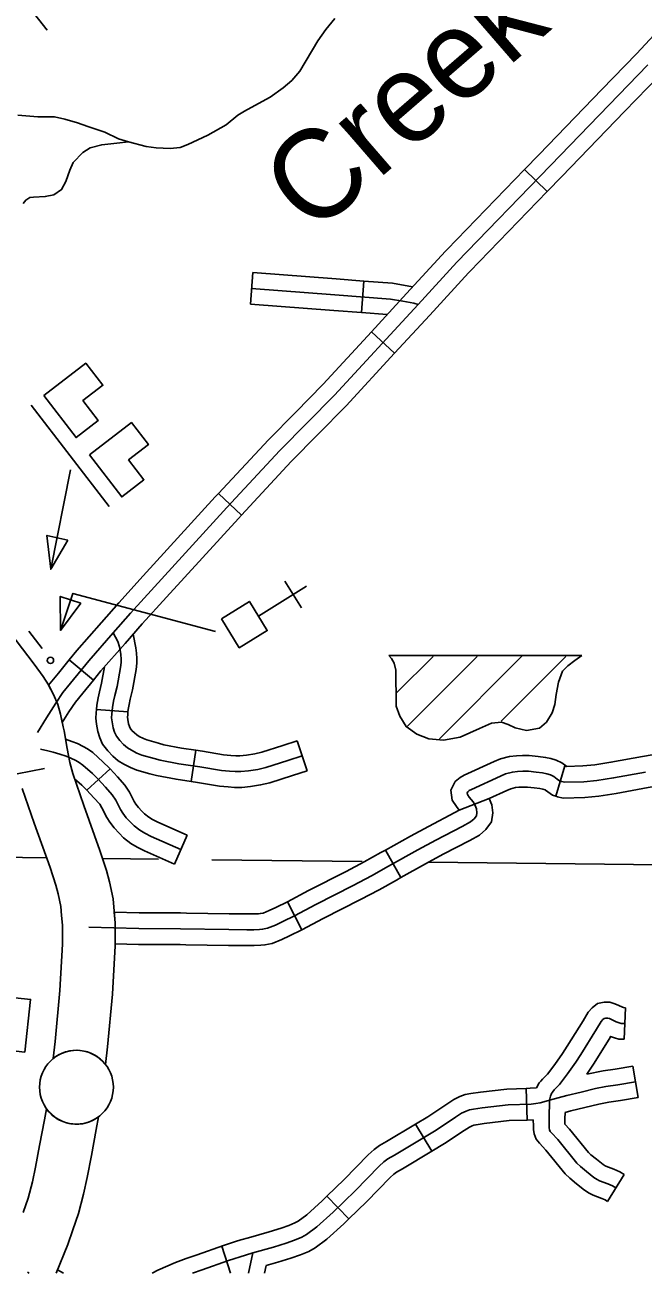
# Model space of a CAD drawing. Extents: x -3711 to 825, y -151 to 1050.
# Drawn here: x -2824.2 to -2791.3, y 120.4 to 186.7 of the extents above; entities that cross this region are included whole.
import ezdxf

# ---------------------------------------------------------------- set-up
doc = ezdxf.new("R2010")
doc.units = 0
for name, color, linetype in [('Level 10', 7, 'Continuous'), ('Level 24', 7, 'Continuous'), ('Level 31', 7, 'Continuous'), ('Level 32', 7, 'Continuous'), ('Level 35', 7, 'Continuous'), ('Level 40', 7, 'Continuous'), ('Level 5', 7, 'Continuous'), ('Level 57', 7, 'Continuous'), ('Level 58', 7, 'Continuous')]:
    doc.layers.add(name, color=color, linetype=linetype)

msp = doc.modelspace()

# ---------------------------------------------------------------- linework, layer by layer
at = {"layer": 'Level 10'}
for points in [[(-2819.879, 131.44), (-2819.776, 132.369), (-2819.516, 135.167), (-2819.367, 137.747), (-2819.367, 138.733), (-2819.367, 138.973), (-2819.42, 139.588), (-2819.476, 140.244), (-2819.669, 141.14), (-2819.821, 141.749), (-2820.181, 142.818), (-2821.029, 145.194), (-2821.623, 146.905), (-2821.768, 147.493), (-2821.872, 147.946), (-2821.952, 148.422), (-2821.973, 148.548), (-2822.085, 149.176), (-2822.127, 149.378), (-2822.27, 150.058), (-2822.417, 150.579), (-2822.639, 151.095), (-2822.907, 151.61), (-2823.201, 152.051), (-2823.664, 152.707), (-2825.611, 155.235)], [(-2824.312, 146.108), (-2823.673, 144.264), (-2822.829, 141.899), (-2822.512, 140.961), (-2822.399, 140.506), (-2822.253, 139.829), (-2822.212, 139.348), (-2822.169, 138.851), (-2822.169, 138.733), (-2822.169, 137.828), (-2822.31, 135.377), (-2822.563, 132.654), (-2822.664, 131.751), (-2822.518, 131.858), (-2822.335, 131.971), (-2822.164, 132.048), (-2821.969, 132.115), (-2821.783, 132.157), (-2821.573, 132.189), (-2821.363, 132.192), (-2821.129, 132.173), (-2820.927, 132.13), (-2820.748, 132.072), (-2820.6, 132.009), (-2820.433, 131.92), (-2820.289, 131.83), (-2820.153, 131.721), (-2820.032, 131.612), (-2819.879, 131.44)], [(-2824.256, 123.57), (-2823.995, 124.331), (-2823.769, 125.198), (-2823.598, 125.99), (-2823.387, 127.13), (-2823.123, 128.498), (-2823.016, 129.084), (-2822.897, 128.927), (-2822.766, 128.792), (-2822.635, 128.684), (-2822.48, 128.572), (-2822.322, 128.483), (-2822.152, 128.402), (-2821.955, 128.336), (-2821.72, 128.286), (-2821.511, 128.267), (-2821.291, 128.271), (-2821.098, 128.29), (-2820.901, 128.332), (-2820.723, 128.394), (-2820.542, 128.475), (-2820.391, 128.56), (-2820.244, 128.665)], [(-2820.244, 128.665), (-2820.369, 127.98), (-2820.633, 126.609), (-2820.851, 125.439), (-2821.042, 124.549), (-2821.311, 123.522), (-2821.61, 122.647), (-2821.887, 121.868), (-2822.501, 120.355)]]:
    msp.add_lwpolyline(points, dxfattribs=at)
at = {"layer": 'Level 24'}
msp.add_circle((-2821.424, 130.231), 1.961, dxfattribs=at)
at = {"layer": 'Level 31'}
for p, q in [((-2796.401, 177.83), (-2797.609, 179)), ((-2804.512, 169.242), (-2805.75, 170.38)), ((-2813.878, 161.784), (-2812.646, 160.64)), ((-2821.816, 152.936), (-2820.516, 151.871)), ((-2809.448, 138.591), (-2810.212, 140.089))]:
    msp.add_line(p, q, dxfattribs=at)
for points in [[(-2793.495, 183.253), (-2791.659, 185.153), (-2790.026, 186.902), (-2789.483, 187.534)], [(-2788.208, 186.439), (-2788.774, 185.78), (-2790.44, 183.995), (-2792.287, 182.085)], [(-2791.05, 184.574), (-2796.232, 179.213), (-2801.2, 174.086), (-2803.268, 171.837), (-2807.702, 167.016), (-2810.613, 164.064), (-2813.427, 161.034), (-2818.551, 155.421), (-2819.467, 154.375), (-2820.763, 152.896), (-2821.734, 151.711), (-2822.141, 151.206), (-2822.529, 150.643), (-2823.014, 149.866), (-2823.498, 149.09)], [(-2797.609, 179), (-2796.836, 179.798), (-2793.495, 183.253)], [(-2792.287, 182.085), (-2795.628, 178.629), (-2796.401, 177.83)], [(-2797.609, 179), (-2801.727, 174.75)], [(-2796.401, 177.83), (-2800.519, 173.58)], [(-2801.727, 174.75), (-2801.811, 174.663), (-2803.886, 172.406), (-2805.75, 170.38)], [(-2800.519, 173.58), (-2800.589, 173.508), (-2802.649, 171.268), (-2804.512, 169.242)], [(-2805.75, 170.38), (-2808.31, 167.596), (-2809.789, 166.096)], [(-2808.592, 164.916), (-2807.093, 166.436), (-2804.512, 169.242)], [(-2809.789, 166.096), (-2811.22, 164.645), (-2813.878, 161.784)], [(-2812.646, 160.64), (-2810.005, 163.482), (-2808.592, 164.916)], [(-2813.878, 161.784), (-2814.045, 161.603), (-2817.874, 157.409)], [(-2812.646, 160.64), (-2812.809, 160.464), (-2816.632, 156.276)], [(-2817.874, 157.409), (-2819.177, 155.981), (-2820.099, 154.929), (-2821.405, 153.439), (-2821.816, 152.936)], [(-2816.632, 156.276), (-2817.924, 154.86), (-2818.835, 153.821), (-2820.122, 152.352), (-2820.516, 151.871)], [(-2822.902, 151.601), (-2822.386, 152.241), (-2821.816, 152.936)], [(-2820.516, 151.871), (-2821.081, 151.181), (-2821.467, 150.703), (-2821.826, 150.181), (-2822.178, 149.618), (-2822.27, 150.058), (-2822.417, 150.579), (-2822.639, 151.095), (-2822.902, 151.601)], [(-2810.212, 140.089), (-2810.829, 139.786), (-2811.181, 139.619), (-2811.506, 139.489), (-2811.658, 139.459), (-2811.752, 139.449), (-2812.014, 139.438), (-2812.362, 139.438), (-2813.312, 139.451), (-2815.582, 139.486)], [(-2809.83, 139.34), (-2810.463, 139.03), (-2810.844, 138.848), (-2811.266, 138.68), (-2811.532, 138.627), (-2811.69, 138.61), (-2811.996, 138.597), (-2812.368, 138.597), (-2813.324, 138.61), (-2815.901, 138.65), (-2818.105, 138.663), (-2820.768, 138.733)], [(-2815.582, 139.486), (-2815.891, 139.491), (-2818.092, 139.504), (-2819.416, 139.539), (-2819.367, 138.973), (-2819.367, 137.856)], [(-2815.608, 137.805), (-2813.336, 137.77), (-2812.374, 137.756), (-2811.978, 137.756), (-2811.628, 137.772), (-2811.405, 137.795), (-2811.026, 137.871), (-2810.508, 138.077), (-2810.097, 138.273), (-2809.448, 138.591)], [(-2819.367, 137.856), (-2818.119, 137.823), (-2815.91, 137.81), (-2815.608, 137.805)]]:
    msp.add_lwpolyline(points, dxfattribs=at)
at = {"layer": 'Level 32'}
for p, q in [((-2812.181, 171.849), (-2812.052, 173.525)), ((-2806.28, 171.395), (-2806.151, 173.071)), ((-2818.689, 150.182), (-2820.366, 150.311)), ((-2809.69, 148.638), (-2809.166, 147.041)), ((-2815.081, 148.137), (-2815.335, 146.475)), ((-2795.947, 145.696), (-2795.463, 147.306)), ((-2819.627, 147.146), (-2820.869, 146.012)), ((-2799.481, 145.571), (-2801.077, 144.959)), ((-2815.534, 143.624), (-2816.218, 142.088)), ((-2804.186, 141.368), (-2805.006, 142.835)), ((-2792.237, 134.456), (-2792.307, 132.776)), ((-2791.851, 131.35), (-2791.568, 129.692)), ((-2797.524, 130.167), (-2797.466, 128.487)), ((-2803.407, 128.267), (-2802.542, 126.825)), ((-2792.318, 125.594), (-2793.203, 124.165)), ((-2808.113, 124.436), (-2806.943, 123.229)), ((-2813.697, 121.785), (-2813.24, 120.355))]:
    msp.add_line(p, q, dxfattribs=at)
for points in [[(-2812.052, 173.525), (-2807.623, 173.185), (-2806.151, 173.071)], [(-2812.116, 172.687), (-2807.688, 172.346), (-2804.735, 172.119), (-2804.082, 172.005), (-2803.486, 171.892), (-2803.268, 171.837)], [(-2806.151, 173.071), (-2804.631, 172.954), (-2803.555, 172.767)], [(-2812.181, 171.849), (-2807.752, 171.508), (-2806.28, 171.395)], [(-2806.28, 171.395), (-2804.913, 171.29)], [(-2809.428, 147.839), (-2810.191, 147.589), (-2811.36, 147.219), (-2811.789, 147.123), (-2812.278, 147.052), (-2812.684, 147.004), (-2812.994, 147.004), (-2813.292, 147.028), (-2813.721, 147.064), (-2814.865, 147.254), (-2815.984, 147.425), (-2816.972, 147.61), (-2817.288, 147.702), (-2817.947, 147.886), (-2818.21, 147.992), (-2818.5, 148.137), (-2818.711, 148.269), (-2818.922, 148.44), (-2819.119, 148.651), (-2819.304, 148.888), (-2819.396, 149.099), (-2819.475, 149.336), (-2819.528, 149.653), (-2819.554, 149.864), (-2819.541, 150.075), (-2819.514, 150.417), (-2819.449, 150.747), (-2819.383, 151.05), (-2819.264, 151.525), (-2819.08, 152.54), (-2819.053, 152.804), (-2819.053, 152.988), (-2819.067, 153.225), (-2819.093, 153.45), (-2819.132, 153.634), (-2819.225, 153.911), (-2819.467, 154.375)], [(-2818.689, 150.182), (-2818.68, 150.302), (-2818.626, 150.575), (-2818.564, 150.859), (-2818.442, 151.348), (-2818.247, 152.423), (-2818.213, 152.762), (-2818.213, 153.011), (-2818.229, 153.298), (-2818.263, 153.587), (-2818.415, 154.3)], [(-2820.366, 150.311), (-2820.349, 150.532), (-2820.271, 150.919), (-2820.201, 151.241), (-2820.086, 151.702), (-2819.928, 152.573)], [(-2815.335, 146.475), (-2816.125, 146.596), (-2817.168, 146.791), (-2817.519, 146.894), (-2818.217, 147.089), (-2818.555, 147.224), (-2818.912, 147.403), (-2819.201, 147.584), (-2819.496, 147.824), (-2819.759, 148.105), (-2820.032, 148.455), (-2820.181, 148.797), (-2820.293, 149.133), (-2820.36, 149.532), (-2820.398, 149.838), (-2820.379, 150.133), (-2820.366, 150.311)], [(-2815.081, 148.137), (-2815.843, 148.254), (-2816.777, 148.428), (-2817.057, 148.51), (-2817.676, 148.684), (-2817.865, 148.759), (-2818.088, 148.871), (-2818.221, 148.954), (-2818.347, 149.056), (-2818.479, 149.197), (-2818.575, 149.321), (-2818.61, 149.401), (-2818.656, 149.54), (-2818.696, 149.774), (-2818.71, 149.89), (-2818.702, 150.016), (-2818.689, 150.182)], [(-2819.627, 147.146), (-2819.679, 147.203), (-2820.001, 147.511), (-2820.56, 148.015), (-2820.838, 148.206), (-2821.066, 148.337), (-2821.373, 148.49), (-2821.678, 148.612), (-2822.005, 148.725)], [(-2809.69, 148.638), (-2810.449, 148.389), (-2811.578, 148.031), (-2811.942, 147.95), (-2812.388, 147.885), (-2812.733, 147.844), (-2812.96, 147.844), (-2813.223, 147.866), (-2813.617, 147.898), (-2814.732, 148.084), (-2815.081, 148.137)], [(-2815.876, 142.856), (-2817.458, 143.559), (-2817.796, 143.725), (-2818.055, 143.885), (-2818.361, 144.121), (-2818.551, 144.312), (-2818.78, 144.554), (-2818.958, 144.795), (-2819.085, 144.986), (-2819.34, 145.495), (-2819.518, 145.775), (-2819.874, 146.17), (-2820.281, 146.615), (-2820.573, 146.895), (-2821.082, 147.354), (-2821.285, 147.494), (-2821.463, 147.595), (-2821.718, 147.723), (-2821.972, 147.824), (-2822.303, 147.939), (-2822.656, 148.041), (-2822.954, 148.111), (-2823.334, 148.188)], [(-2795.463, 147.306), (-2795.418, 147.293), (-2795.376, 147.282), (-2794.514, 147.309), (-2793.865, 147.37), (-2793.015, 147.498), (-2791.329, 147.807), (-2790.001, 148.039)], [(-2801.077, 144.959), (-2801.227, 145.142), (-2801.451, 145.492), (-2801.526, 146.011), (-2801.296, 146.47), (-2801.032, 146.691), (-2800.811, 146.811), (-2799.22, 147.539), (-2798.891, 147.676), (-2798.413, 147.807), (-2798.041, 147.851), (-2797.714, 147.864), (-2797.353, 147.864), (-2796.889, 147.814), (-2796.488, 147.762), (-2796.208, 147.692), (-2795.931, 147.615), (-2795.619, 147.469), (-2795.368, 147.277), (-2795.463, 147.306)], [(-2824.57, 146.887), (-2823.131, 147.168)], [(-2820.869, 146.012), (-2820.882, 146.028), (-2821.145, 146.279), (-2821.524, 146.62)], [(-2815.534, 143.624), (-2817.102, 144.321), (-2817.39, 144.462), (-2817.576, 144.577), (-2817.804, 144.753), (-2817.949, 144.898), (-2818.134, 145.094), (-2818.27, 145.278), (-2818.357, 145.409), (-2818.607, 145.91), (-2818.846, 146.286), (-2819.251, 146.735), (-2819.627, 147.146)], [(-2809.166, 147.041), (-2809.933, 146.789), (-2811.141, 146.406), (-2811.637, 146.296), (-2812.168, 146.218), (-2812.634, 146.163), (-2813.027, 146.163), (-2813.36, 146.19), (-2813.825, 146.229), (-2814.997, 146.423), (-2815.335, 146.475)], [(-2809.83, 139.34), (-2808.704, 139.937), (-2806.709, 140.954), (-2805.739, 141.462), (-2804.832, 141.97), (-2803.272, 142.841), (-2802.319, 143.352), (-2800.922, 144.084), (-2800.479, 144.328), (-2800.279, 144.495), (-2800.169, 144.65), (-2800.146, 144.817), (-2800.169, 145.027), (-2800.235, 145.194), (-2800.346, 145.393), (-2800.545, 145.637), (-2800.645, 145.793), (-2800.656, 145.87), (-2800.623, 145.937), (-2800.557, 145.992), (-2800.435, 146.059), (-2798.883, 146.769), (-2798.617, 146.879), (-2798.251, 146.979), (-2797.974, 147.013), (-2797.697, 147.024), (-2797.398, 147.024), (-2796.988, 146.979), (-2796.644, 146.935), (-2796.423, 146.879), (-2796.223, 146.824), (-2796.057, 146.746), (-2795.869, 146.602), (-2795.747, 146.513), (-2795.636, 146.48), (-2795.461, 146.439), (-2794.461, 146.469), (-2793.763, 146.536), (-2792.876, 146.669), (-2791.181, 146.979)], [(-2816.218, 142.088), (-2817.814, 142.798), (-2818.203, 142.988), (-2818.534, 143.192), (-2818.917, 143.489), (-2819.154, 143.726), (-2819.426, 144.013), (-2819.647, 144.313), (-2819.814, 144.564), (-2820.072, 145.081), (-2820.189, 145.265), (-2820.496, 145.605), (-2820.869, 146.012)], [(-2799.481, 145.571), (-2798.546, 145.998), (-2798.344, 146.083), (-2798.09, 146.152), (-2797.907, 146.174), (-2797.68, 146.183), (-2797.443, 146.183), (-2797.087, 146.145), (-2796.801, 146.108), (-2796.637, 146.067), (-2796.516, 146.033), (-2796.496, 146.023), (-2796.372, 145.929), (-2796.126, 145.75), (-2795.947, 145.696)], [(-2795.947, 145.696), (-2795.853, 145.668), (-2795.546, 145.595), (-2794.409, 145.63), (-2793.661, 145.701), (-2792.738, 145.839), (-2791.033, 146.152), (-2789.712, 146.383)], [(-2804.186, 141.368), (-2802.868, 142.104), (-2801.925, 142.61), (-2800.524, 143.344), (-2800.003, 143.631), (-2799.658, 143.919), (-2799.363, 144.332), (-2799.3, 144.805), (-2799.345, 145.231), (-2799.481, 145.571)], [(-2805.006, 142.835), (-2803.675, 143.579), (-2802.712, 144.095), (-2801.32, 144.825), (-2801.077, 144.959)], [(-2810.212, 140.089), (-2809.092, 140.683), (-2807.095, 141.7), (-2806.139, 142.201), (-2805.242, 142.704), (-2805.006, 142.835)], [(-2809.448, 138.591), (-2808.316, 139.191), (-2806.323, 140.207), (-2805.338, 140.723), (-2804.421, 141.237), (-2804.186, 141.368)], [(-2792.237, 134.456), (-2792.341, 134.46), (-2792.4, 134.483), (-2792.594, 134.572), (-2792.801, 134.67), (-2793.073, 134.744), (-2793.371, 134.744), (-2793.724, 134.674), (-2794.02, 134.451), (-2794.218, 134.218), (-2794.495, 133.759), (-2795.334, 132.415), (-2795.583, 132.029), (-2795.996, 131.446), (-2796.388, 130.931), (-2796.66, 130.65), (-2796.746, 130.548)], [(-2792.272, 133.616), (-2792.475, 133.624), (-2792.577, 133.65), (-2792.729, 133.709), (-2792.949, 133.811), (-2793.093, 133.878), (-2793.186, 133.904), (-2793.288, 133.904), (-2793.372, 133.887), (-2793.44, 133.836), (-2793.533, 133.726), (-2793.778, 133.32), (-2794.624, 131.965), (-2794.886, 131.559), (-2795.318, 130.949), (-2795.749, 130.382), (-2796.037, 130.085), (-2796.13, 129.975), (-2796.172, 129.899), (-2796.231, 129.747), (-2796.278, 129.534)], [(-2792.307, 132.776), (-2792.596, 132.788), (-2792.832, 132.847), (-2793.034, 132.926), (-2793.062, 132.88), (-2793.914, 131.514), (-2794.295, 130.925)], [(-2791.851, 131.35), (-2792.782, 131.191), (-2793.421, 131.093), (-2794.295, 130.925)], [(-2791.709, 130.521), (-2792.648, 130.361), (-2793.278, 130.265), (-2793.833, 130.158), (-2794.59, 129.976), (-2795.359, 129.795), (-2796.278, 129.534), (-2796.451, 129.484), (-2796.773, 129.408), (-2797.012, 129.357), (-2797.258, 129.336), (-2798.485, 129.293), (-2799.851, 129.133), (-2800.32, 129.069), (-2800.534, 129.026), (-2800.715, 128.962), (-2800.95, 128.844), (-2801.281, 128.631), (-2802.305, 127.947), (-2804.514, 126.623), (-2804.866, 126.42), (-2805.079, 126.271), (-2805.329, 126.041), (-2806.604, 124.727), (-2807.784, 123.584), (-2808.641, 122.803), (-2809.188, 122.403), (-2809.445, 122.26), (-2809.826, 122.099), (-2810.282, 121.937), (-2810.948, 121.737), (-2812.052, 121.422), (-2812.442, 121.308), (-2813.337, 121.022), (-2814.736, 120.518), (-2815.258, 120.355)], [(-2797.524, 130.167), (-2798.549, 130.132), (-2799.957, 129.967), (-2800.46, 129.898), (-2800.757, 129.838), (-2801.044, 129.737), (-2801.367, 129.575), (-2801.742, 129.333), (-2802.755, 128.658), (-2803.407, 128.267)], [(-2796.964, 130.205), (-2797.309, 130.175), (-2797.524, 130.167)], [(-2796.746, 130.548), (-2796.825, 130.455), (-2796.964, 130.205)], [(-2792.761, 124.88), (-2792.934, 124.987), (-2793.181, 125.094), (-2793.618, 125.259), (-2793.75, 125.325), (-2793.923, 125.441), (-2794.311, 125.746), (-2794.641, 126.019), (-2794.822, 126.2), (-2795.845, 127.446), (-2796.175, 127.801), (-2796.241, 127.884), (-2796.274, 127.974), (-2796.29, 128.073), (-2796.298, 128.214), (-2796.307, 128.56), (-2796.278, 129.534)], [(-2791.568, 129.692), (-2792.514, 129.531), (-2793.135, 129.436), (-2793.655, 129.336), (-2794.396, 129.159), (-2795.147, 128.981), (-2795.456, 128.893)], [(-2792.318, 125.594), (-2792.543, 125.734), (-2792.865, 125.873), (-2793.281, 126.03), (-2793.327, 126.054), (-2793.429, 126.122), (-2793.783, 126.401), (-2794.075, 126.641), (-2794.199, 126.765), (-2795.211, 128), (-2795.459, 128.266), (-2795.466, 128.558), (-2795.456, 128.893)], [(-2803.407, 128.267), (-2804.94, 127.348), (-2805.318, 127.13), (-2805.607, 126.927), (-2805.916, 126.644), (-2807.199, 125.322), (-2808.113, 124.436)], [(-2797.466, 128.487), (-2798.421, 128.454), (-2799.745, 128.299), (-2800.181, 128.239), (-2800.31, 128.213), (-2800.386, 128.187), (-2800.532, 128.113), (-2800.819, 127.928), (-2801.855, 127.237), (-2802.542, 126.825)], [(-2797.146, 128.498), (-2797.466, 128.487)], [(-2793.203, 124.165), (-2793.325, 124.24), (-2793.497, 124.315), (-2793.956, 124.488), (-2794.173, 124.597), (-2794.418, 124.76), (-2794.839, 125.092), (-2795.207, 125.396), (-2795.446, 125.635), (-2796.478, 126.893), (-2796.812, 127.252), (-2796.983, 127.467), (-2797.09, 127.76), (-2797.127, 127.979), (-2797.138, 128.179), (-2797.146, 128.498)], [(-2802.542, 126.825), (-2804.088, 125.898), (-2804.414, 125.71), (-2804.552, 125.614), (-2804.743, 125.438), (-2806.01, 124.132), (-2806.943, 123.229)], [(-2808.113, 124.436), (-2808.36, 124.197), (-2809.174, 123.455), (-2809.642, 123.113), (-2809.815, 123.017), (-2810.131, 122.882), (-2810.544, 122.736), (-2811.184, 122.543), (-2812.286, 122.23), (-2812.688, 122.112), (-2812.967, 122.023)], [(-2806.943, 123.229), (-2807.209, 122.972), (-2808.108, 122.151), (-2808.734, 121.694), (-2809.075, 121.504), (-2809.52, 121.315), (-2810.021, 121.137), (-2810.712, 120.93), (-2811.339, 120.751)], [(-2812.967, 122.023), (-2813.608, 121.818), (-2815.004, 121.315), (-2815.592, 121.131), (-2816.158, 120.915), (-2817.105, 120.5), (-2817.405, 120.355)], [(-2812.052, 121.422), (-2812.288, 120.355)], [(-2811.339, 120.751), (-2811.427, 120.355)], [(-2823.941, 120.355), (-2824.028, 120.4)], [(-2822.11, 120.355), (-2822.433, 120.522)]]:
    msp.add_lwpolyline(points, dxfattribs=at)
at = {"layer": 'Level 35'}
for points in [[(-2824.54, 181.884), (-2823.472, 181.807), (-2822.598, 181.807), (-2822.035, 181.671), (-2821.375, 181.476), (-2820.812, 181.282), (-2819.919, 180.991), (-2819.181, 180.641), (-2818.654, 180.48), (-2817.725, 180.233), (-2817.181, 180.155), (-2816.443, 180.116), (-2815.919, 180.175), (-2815.511, 180.33), (-2814.443, 180.835), (-2813.472, 181.379), (-2812.851, 181.884), (-2812.501, 182.098), (-2811.744, 182.506), (-2811.123, 182.856), (-2810.443, 183.342), (-2809.977, 183.73), (-2809.55, 184.236), (-2808.599, 185.848), (-2808.172, 186.451), (-2807.686, 187.034)], [(-2824.254, 177.198), (-2824.116, 177.381), (-2823.91, 177.519), (-2823.704, 177.542), (-2823.084, 177.565), (-2822.626, 177.657), (-2822.213, 177.932), (-2821.984, 178.368), (-2821.777, 178.965), (-2821.594, 179.378), (-2821.089, 179.906), (-2820.699, 180.159), (-2820.08, 180.319), (-2819.277, 180.411), (-2818.654, 180.48)]]:
    msp.add_lwpolyline(points, dxfattribs=at)
at = {"layer": 'Level 40'}
msp.add_line((-2823.898, 187.571), (-2822.977, 186.412), dxfattribs=at)
at = {"layer": 'Level 5'}
for points in [[(-2828.203, 142.488), (-2823.006, 142.425)], [(-2820.037, 142.389), (-2817.066, 142.354)], [(-2814.233, 142.321), (-2806.245, 142.229)], [(-2802.706, 142.189), (-2782.456, 141.957)]]:
    msp.add_lwpolyline(points, dxfattribs=at)
at = {"layer": 'Level 57'}
for p, q in [((-2809.189, 156.858), (-2811.756, 155.272)), ((-2810.346, 157.132), (-2809.462, 155.701)), ((-2804.818, 153.169), (-2794.565, 153.169)), ((-2804.396, 151.2), (-2802.466, 153.13)), ((-2803.824, 149.418), (-2800.125, 153.117)), ((-2802.134, 148.754), (-2797.753, 153.135)), ((-2798.851, 149.684), (-2795.42, 153.115))]:
    msp.add_line(p, q, dxfattribs=at)
for points in [[(-2821.197, 155.962), (-2822.284, 156.316), (-2822.271, 154.508)], [(-2813.722, 155.128), (-2812.234, 156.047), (-2811.281, 154.503), (-2812.769, 153.584)]]:
    msp.add_lwpolyline(points, close=True, dxfattribs=at)
for points in [[(-2822.271, 154.508), (-2821.609, 156.477), (-2814.03, 154.446)], [(-2804.818, 153.169), (-2804.673, 153.008), (-2804.535, 152.763), (-2804.443, 152.396), (-2804.443, 151.844), (-2804.427, 151.124), (-2804.427, 150.481), (-2804.244, 149.945), (-2803.891, 149.393), (-2803.34, 148.995), (-2802.696, 148.75), (-2801.915, 148.673), (-2801.027, 148.842), (-2800, 149.301), (-2799.372, 149.577), (-2798.836, 149.623), (-2798.469, 149.516), (-2798.101, 149.332), (-2797.504, 149.194), (-2796.814, 149.317), (-2796.447, 149.623), (-2796.14, 150.129), (-2796.002, 150.573), (-2795.926, 151.094), (-2795.803, 151.752), (-2795.589, 152.35), (-2795.298, 152.625), (-2794.93, 152.916), (-2794.565, 153.169)]]:
    msp.add_lwpolyline(points, dxfattribs=at)
msp.add_circle((-2822.807, 152.915), 0.168, dxfattribs=at)
at = {"layer": 'Level 58'}
msp.add_line((-2822.793, 157.757), (-2821.744, 163.046), dxfattribs=at)
for points in [[(-2823.161, 166.991), (-2821.441, 164.758), (-2820.263, 165.665), (-2821.077, 166.722), (-2820.022, 167.535), (-2820.928, 168.711)], [(-2820.739, 163.837), (-2819.019, 161.604), (-2817.841, 162.511), (-2818.655, 163.568), (-2817.6, 164.38), (-2818.506, 165.557)], [(-2821.874, 159.313), (-2822.991, 159.554), (-2822.793, 157.757)], [(-2824.174, 132.094), (-2823.863, 134.896), (-2825.341, 135.06), (-2825.488, 133.734), (-2826.812, 133.881), (-2826.975, 132.405)]]:
    msp.add_lwpolyline(points, close=True, dxfattribs=at)
for points in [[(-2823.827, 166.478), (-2819.68, 161.094)], [(-2823.961, 154.471), (-2823.254, 153.552)]]:
    msp.add_lwpolyline(points, dxfattribs=at)

# ---------------------------------------------------------------- texts
at = {"layer": 'Level 35'}
msp.add_text('Creek', height=4.7343, rotation=40.90795, dxfattribs=at).set_placement((-2808.876, 175.429))

doc.saveas('drawing.dxf')
